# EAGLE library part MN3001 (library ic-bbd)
Dual 512-Stage BBD
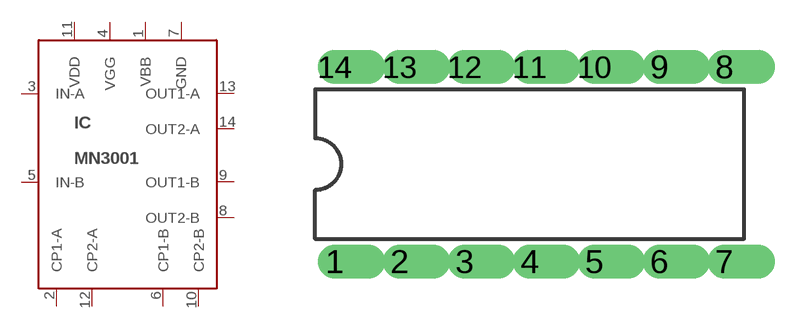
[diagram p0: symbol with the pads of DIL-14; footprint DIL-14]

Designator prefix IC

## MN3001  [DIL-14]
1  VBB
2  CP1-A
3  IN-A
4  VGG
5  IN-B
6  CP1-B
7  GND
8  OUT2-B
9  OUT1-B
10  CP2-B
11  VDD
12  CP2-A
13  OUT1-A
14  OUT2-A

## Footprint DIL-14 (pad centres in mm)
Dual In Line Package
drill 0.813 offset: 1 -7.62,-3.81; 2 -5.08,-3.81; 3 -2.54,-3.81; 4 0,-3.81; 5 2.54,-3.81; 6 5.08,-3.81; 7 7.62,-3.81; 8 7.62,3.81; 9 5.08,3.81; 10 2.54,3.81; 11 0,3.81; 12 -2.54,3.81; 13 -5.08,3.81; 14 -7.62,3.81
